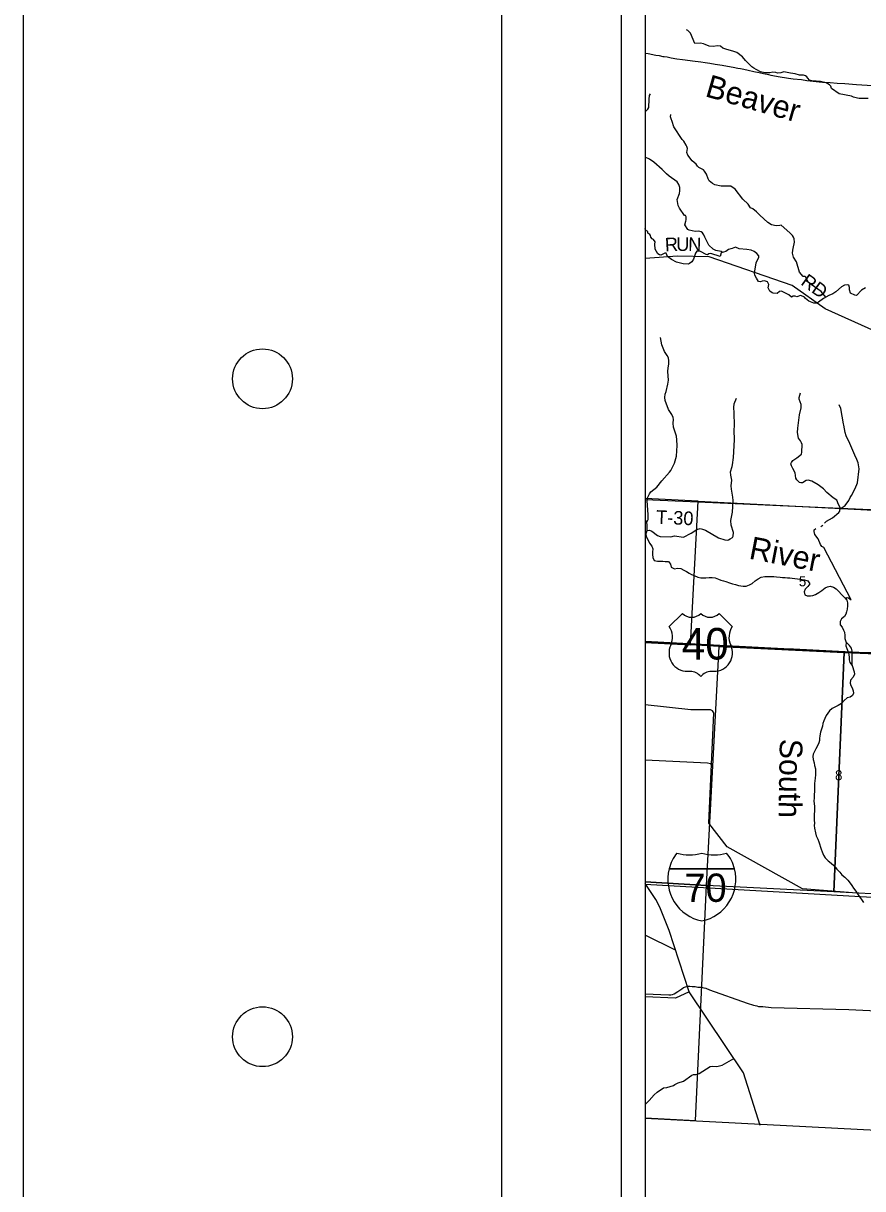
# Model space of a CAD drawing. Extents: x 0 to 40.4, y 0 to 22.
# Drawn here: x 0 to 3.509, y 14.615 to 19.486 of the extents above; entities that cross this region are included whole.
import ezdxf

# ---------------------------------------------------------------- set-up
doc = ezdxf.new("R2010")
doc.units = 0
for name, color, linetype in [('GM_X_County', 7, 'Continuous'), ('GM_X_County_Road', 7, 'Continuous'), ('GM_X_Interstate_Route', 7, 'Continuous'), ('GM_X_Interstate_Shield', 7, 'Continuous'), ('GM_X_Major_River', 7, 'Continuous'), ('GM_X_Major_River_Text', 7, 'Continuous'), ('GM_X_Minor_River', 7, 'Continuous'), ('GM_X_Minor_River_Text', 7, 'Continuous'), ('GM_X_Section', 7, 'Continuous'), ('GM_X_Section_Text', 7, 'Continuous'), ('GM_X_Township_Road', 7, 'Continuous'), ('GM_X_Township_Road_Text', 7, 'Continuous'), ('GM_X_US_Route', 7, 'Continuous'), ('GM_X_US_Shield', 7, 'Continuous'), ('SH_Border', 7, 'Continuous'), ('SH_Cut_Line', 7, 'Continuous'), ('SH_Data', 7, 'Continuous')]:
    doc.layers.add(name, color=color, linetype=linetype)

msp = doc.modelspace()

# ---------------------------------------------------------------- linework, layer by layer
at = {"layer": 'GM_X_County'}
for points in [[(2.6, 14.9098), (3.7816, 14.849), (3.7947, 14.8444), (4.3781, 14.8049), (4.5187, 14.7962), (4.7718, 14.7855), (4.9113, 14.7777), (5.1259, 14.7632), (5.4221, 14.7453), (5.6303, 14.7317), (5.757, 14.7237), (5.765, 14.7235), (5.7951, 14.7228), (5.8513, 14.7168), (5.9456, 14.7103), (6.2034, 14.693), (6.2494, 14.69), (6.369, 14.682), (6.4224, 14.6785), (7.5441, 14.6124), (8.0846, 14.9692), (9.4, 14.8681)], [(2.6, 14.9098), (2.6, 14.9098)]]:
    msp.add_lwpolyline(points, dxfattribs=at)
at = {"layer": 'GM_X_County_Road'}
msp.add_lwpolyline([(3.6855, 19.2158), (3.4837, 19.2291), (3.4349, 19.2324), (3.402, 19.2344), (3.3734, 19.2363), (3.3412, 19.2388), (3.3273, 19.24), (3.3014, 19.2425), (3.2749, 19.2458), (3.2536, 19.2489), (3.2184, 19.2527), (3.1992, 19.2553), (3.1899, 19.257), (3.1638, 19.2613), (3.1408, 19.2649), (3.1263, 19.2682), (3.1164, 19.2702), (3.094, 19.2748), (3.0769, 19.2783), (3.0543, 19.2827), (3.0301, 19.288), (3.0117, 19.2922), (2.9984, 19.2949), (2.9865, 19.2973), (2.9669, 19.3013), (2.9435, 19.3056), (2.9219, 19.3092), (2.8921, 19.3139), (2.87, 19.3174), (2.85, 19.3207), (2.8323, 19.3229), (2.7979, 19.3278), (2.7666, 19.3318), (2.7559, 19.3337), (2.7321, 19.3365), (2.7084, 19.3403), (2.6915, 19.3436), (2.6794, 19.3454), (2.6746, 19.3463), (2.6591, 19.3494), (2.6444, 19.3514), (2.6119, 19.3579), (2.6, 19.3601)], dxfattribs=at)
at = {"layer": 'GM_X_Interstate_Route'}
msp.add_lwpolyline([(2.6, 15.8882), (3.6952, 15.8249), (3.7567, 15.8254), (4.0998, 15.8089), (4.2342, 15.8011)], dxfattribs=at)
at = {"layer": 'GM_X_Interstate_Shield'}
for p, q in [((2.6999, 15.9513), (2.9732, 15.9513)), ((2.9732, 15.9513), (2.6999, 15.9513)), ((2.9732, 15.9513), (2.6999, 15.9513))]:
    msp.add_line(p, q, dxfattribs=at)
for centre, start, end in [((2.872, 15.9078), 141.669, 165.8066), ((2.7846, 16.1877), 253.0091, 286.9909), ((2.8884, 16.1877), 253.0091, 286.9909), ((2.801, 15.9078), 14.1934, 38.331), ((2.872, 15.9078), 165.8066, 258.463), ((2.801, 15.9078), 281.537, 14.1934)]:
    msp.add_arc(centre, 0.1776, start, end, dxfattribs=at)
at = {"layer": 'GM_X_Major_River'}
for points in [[(2.6, 17.4091), (2.6035, 17.4036), (2.6073, 17.3903), (2.6073, 17.377), (2.6065, 17.3649), (2.602, 17.352), (2.6042, 17.3402), (2.6107, 17.3285), (2.6183, 17.3125), (2.627, 17.3008), (2.6312, 17.2886), (2.6304, 17.2757), (2.6308, 17.2659), (2.6315, 17.253), (2.6376, 17.2405), (2.6516, 17.2378), (2.6611, 17.2374), (2.674, 17.2374), (2.6835, 17.2366), (2.6968, 17.2359), (2.7059, 17.2253), (2.7089, 17.212), (2.7229, 17.2063), (2.7355, 17.2078), (2.7483, 17.2067), (2.762, 17.2002), (2.7726, 17.1941), (2.7836, 17.1881), (2.7939, 17.1816), (2.8049, 17.1774), (2.8193, 17.171), (2.8322, 17.1676), (2.8424, 17.1679), (2.8538, 17.1687), (2.8667, 17.1694), (2.8796, 17.1691), (2.8925, 17.1679), (2.9069, 17.163), (2.9164, 17.1588), (2.9266, 17.1554), (2.9368, 17.1523), (2.952, 17.1467), (2.9645, 17.1436), (2.9774, 17.1402), (2.9899, 17.1364), (2.9998, 17.1341), (3.0093, 17.1337), (3.0218, 17.1333), (3.0362, 17.1383), (3.0468, 17.144), (3.0593, 17.155), (3.0722, 17.1633), (3.0848, 17.1705), (3.0996, 17.1731), (3.1128, 17.1743), (3.1257, 17.1735), (3.1379, 17.1731), (3.1489, 17.1724), (3.1637, 17.1705), (3.1735, 17.1697), (3.1849, 17.1689), (3.1951, 17.1686), (3.2046, 17.1674), (3.2149, 17.167), (3.2255, 17.1655), (3.2365, 17.1644), (3.2471, 17.1629), (3.2566, 17.1613), (3.2664, 17.1598), (3.2797, 17.156), (3.2877, 17.1431), (3.2797, 17.1325), (3.2687, 17.1207), (3.2649, 17.1101), (3.2672, 17.0972), (3.2771, 17.0927), (3.2911, 17.0927), (3.3006, 17.0942), (3.3116, 17.098), (3.3264, 17.1063), (3.3389, 17.115), (3.3525, 17.1268)], [(3.3525, 17.1268), (3.362, 17.1306), (3.3726, 17.1332), (3.387, 17.1287), (3.3984, 17.1222), (3.4094, 17.1108), (3.4208, 17.0987), (3.4326, 17.0862), (3.4428, 17.0752), (3.4455, 17.063), (3.4454, 17.0509), (3.4447, 17.0372), (3.442, 17.0255), (3.4382, 17.0156), (3.4329, 17.0061), (3.4208, 16.9974), (3.4151, 16.9853), (3.4151, 16.972), (3.4231, 16.9618), (3.4295, 16.95), (3.4333, 16.9405), (3.4341, 16.9272), (3.434, 16.914), (3.4394, 16.898)], [(3.4394, 16.898), (3.4386, 16.8844), (3.4431, 16.8726), (3.4485, 16.859), (3.4507, 16.848), (3.4519, 16.8351), (3.4526, 16.8256), (3.4557, 16.8146), (3.4651, 16.8013)], [(3.4651, 16.8013), (3.4648, 16.8142), (3.4648, 16.8616), (3.4629, 16.8737), (3.4538, 16.8859), (3.4428, 16.8969), (3.4394, 16.898)], [(3.4651, 16.8013), (3.4735, 16.7747), (3.4742, 16.7653), (3.4697, 16.7531), (3.4587, 16.7402), (3.456, 16.7277), (3.4591, 16.7182), (3.4644, 16.7084), (3.4697, 16.6958), (3.4704, 16.686), (3.4659, 16.6761), (3.4564, 16.6697), (3.4443, 16.6663), (3.4317, 16.6549), (3.42, 16.6424), (3.4071, 16.634), (3.393, 16.6276), (3.382, 16.6215), (3.3699, 16.612), (3.3627, 16.6026), (3.357, 16.5927), (3.3506, 16.5802), (3.3464, 16.5707), (3.343, 16.5586), (3.3407, 16.5487), (3.3365, 16.5358), (3.3323, 16.5233), (3.3293, 16.5081), (3.3289, 16.4971), (3.3278, 16.4876), (3.3259, 16.4782), (3.3206, 16.4656), (3.313, 16.4539), (3.3069, 16.4429), (3.302, 16.4307), (3.3008, 16.4213), (3.3024, 16.4091), (3.3062, 16.3951), (3.308, 16.3841), (3.3111, 16.3704), (3.3115, 16.3572), (3.3115, 16.3446), (3.3103, 16.3306), (3.3088, 16.3192), (3.308, 16.3082), (3.3073, 16.2965), (3.3073, 16.2862), (3.3069, 16.2764), (3.3061, 16.2604), (3.3057, 16.2468), (3.3054, 16.2361), (3.3076, 16.2119), (3.3076, 16.202), (3.3073, 16.1914), (3.3065, 16.1815), (3.3065, 16.155), (3.3069, 16.1432), (3.3061, 16.133), (3.3069, 16.1212), (3.3114, 16.1022), (3.3148, 16.0893), (3.3209, 16.0757), (3.3254, 16.0651), (3.3285, 16.0556), (3.3323, 16.043), (3.3353, 16.0336), (3.3399, 16.0222), (3.3452, 16.0085), (3.3516, 15.9979), (3.3645, 15.9858), (3.377, 15.9751), (3.388, 15.9653), (3.4005, 15.9501), (3.413, 15.9376), (3.4225, 15.9266), (3.4347, 15.9167), (3.4464, 15.9042), (3.457, 15.8913), (3.4631, 15.8818), (3.4703, 15.8712), (3.4802, 15.8583), (3.4878, 15.8469), (3.4957, 15.8343), (3.5041, 15.8233), (3.5124, 15.8104)]]:
    msp.add_lwpolyline(points, dxfattribs=at)
at = {"layer": 'GM_X_Minor_River'}
for points in [[(3.5326, 19.1712), (3.4943, 19.1721), (3.4871, 19.1729), (3.4708, 19.1775), (3.4617, 19.1817), (3.4113, 19.1917), (3.3792, 19.2138), (3.3758, 19.2233), (3.3709, 19.229), (3.3557, 19.2367), (3.3322, 19.2432), (3.2958, 19.2456), (3.2871, 19.2487), (3.2799, 19.2563), (3.2754, 19.262), (3.2701, 19.2666), (3.2617, 19.2692), (3.2454, 19.2689), (3.2273, 19.2751), (3.2079, 19.277), (3.1787, 19.2824), (3.167, 19.2783), (3.1525, 19.2776), (3.1461, 19.2803), (3.1336, 19.2822), (3.1207, 19.2781), (3.0998, 19.2782), (3.0816, 19.2828), (3.0631, 19.2923), (3.0536, 19.2985), (3.046, 19.3034), (3.0188, 19.3301), (3.0064, 19.3457), (2.9825, 19.3632), (2.9704, 19.3685), (2.9564, 19.372), (2.9408, 19.3759), (2.9245, 19.382), (2.9143, 19.39), (2.9026, 19.3912), (2.8836, 19.389), (2.8673, 19.3905), (2.8503, 19.397), (2.8431, 19.3993), (2.8309, 19.4024), (2.807, 19.4014), (2.7886, 19.4439), (2.7776, 19.4557), (2.7723, 19.458)], [(2.6, 19.1164), (2.6027, 19.1184), (2.6104, 19.1264), (2.6146, 19.1332), (2.6162, 19.1692), (2.6185, 19.1844), (2.6216, 19.1908)], [(3.3552, 18.341), (3.3349, 18.3644), (3.2937, 18.3945), (3.2816, 18.4056), (3.2751, 18.4151), (3.2718, 18.4253), (3.2665, 18.4276), (3.2608, 18.4269), (3.2449, 18.4463), (3.2322, 18.4892), (3.2193, 18.5082), (3.2163, 18.5249), (3.2164, 18.5374), (3.2183, 18.545), (3.2245, 18.5708), (3.223, 18.5848), (3.22, 18.5917), (3.2155, 18.5985), (3.2049, 18.6095), (3.1678, 18.6419), (3.1629, 18.6408), (3.1473, 18.6393), (3.1284, 18.6439), (3.1121, 18.6527), (3.0788, 18.6832), (3.0656, 18.6977), (3.0501, 18.7098), (3.0402, 18.7141), (3.0297, 18.7293), (3.0077, 18.7506), (2.9753, 18.7932), (2.9578, 18.805), (2.9529, 18.805), (2.9457, 18.8054), (2.9173, 18.8051), (2.8915, 18.8109), (2.8816, 18.8163), (2.8676, 18.8277), (2.8624, 18.8361), (2.8556, 18.8554), (2.8481, 18.8676), (2.8435, 18.8733), (2.8246, 18.8829), (2.8178, 18.8893), (2.8129, 18.8966), (2.7955, 18.9114), (2.7777, 18.9346), (2.7744, 18.9456), (2.7767, 18.9631), (2.7745, 18.9714), (2.7707, 18.9767), (2.7609, 18.9931), (2.7548, 18.9999), (2.719, 19.0535), (2.7126, 19.0748), (2.7077, 19.0866), (2.7062, 19.0945), (2.707, 19.1044)], [(2.9228, 18.5285), (2.9171, 18.5317), (2.8947, 18.5367), (2.8841, 18.5421), (2.8656, 18.5588), (2.8498, 18.5919), (2.8453, 18.6021), (2.8392, 18.6105), (2.8335, 18.6143), (2.8241, 18.6166), (2.8093, 18.6163), (2.7842, 18.6209), (2.7782, 18.624), (2.7657, 18.643), (2.7692, 18.6589), (2.7704, 18.6638), (2.7708, 18.6771), (2.7685, 18.6824), (2.7636, 18.6821), (2.7428, 18.7136), (2.7379, 18.7239), (2.7331, 18.7497), (2.7427, 18.7751), (2.7446, 18.7857), (2.7447, 18.8001), (2.7409, 18.8119), (2.7334, 18.8229), (2.6997, 18.8473), (2.6891, 18.8568), (2.6709, 18.8751), (2.6358, 18.9052), (2.6176, 18.9185), (2.6, 18.9262)], [(3.2271, 18.3447), (3.218, 18.3448), (3.2115, 18.3406), (3.1998, 18.3513), (3.1695, 18.3666), (3.1612, 18.3651), (3.1509, 18.3568), (3.135, 18.3572), (3.13, 18.3587), (3.1202, 18.3667), (3.1138, 18.38), (3.1161, 18.3944), (3.1112, 18.4051), (3.0991, 18.4097), (3.0889, 18.4086), (3.0813, 18.4059), (3.0737, 18.4071), (3.0692, 18.4132), (3.065, 18.42), (3.0579, 18.4337), (3.0571, 18.4413), (3.0633, 18.4849), (3.0744, 18.5084), (3.0748, 18.5141), (3.0669, 18.5232), (3.0559, 18.5319), (3.0427, 18.5369), (3.0252, 18.5408), (2.993, 18.5436), (2.9771, 18.5497), (2.963, 18.5452), (2.9573, 18.5429), (2.9482, 18.5407), (2.9376, 18.5324), (2.9178, 18.5271), (2.9128, 18.5112), (2.8738, 18.5243), (2.8662, 18.522), (2.8605, 18.5179), (2.8548, 18.519), (2.8314, 18.532), (2.8162, 18.534), (2.8101, 18.5256), (2.8017, 18.5006), (2.7948, 18.4889), (2.7849, 18.4814), (2.78, 18.4791), (2.7591, 18.4807), (2.7307, 18.4876), (2.7095, 18.4983), (2.6932, 18.5113), (2.6876, 18.5253), (2.6819, 18.5254), (2.6652, 18.5171), (2.6591, 18.5175), (2.653, 18.522), (2.6414, 18.5422), (2.6399, 18.5631), (2.6415, 18.5729), (2.6339, 18.5817), (2.6286, 18.5855), (2.6237, 18.5923), (2.6226, 18.5984), (2.6192, 18.6037), (2.6112, 18.6087), (2.6105, 18.6163), (2.601, 18.6216), (2.6, 18.628)], [(3.5212, 18.3797), (3.5041, 18.3706), (3.4832, 18.348), (3.4756, 18.3495), (3.4578, 18.3575), (3.4544, 18.3723), (3.4533, 18.3811), (3.4507, 18.3917), (3.4446, 18.3925), (3.4336, 18.391), (3.4211, 18.3842), (3.3971, 18.3631), (3.3842, 18.3552), (3.3682, 18.348), (3.345, 18.3356), (3.3237, 18.3201), (3.315, 18.316), (3.3048, 18.316), (3.2839, 18.324), (3.2703, 18.3351), (3.2658, 18.3408), (3.2609, 18.3442), (3.2484, 18.3488), (3.2332, 18.342), (3.2271, 18.3447)], [(2.6053, 17.3973), (2.6128, 17.4113), (2.6125, 17.4333), (2.6078, 17.4898), (2.6101, 17.5031), (2.6185, 17.5194), (2.6238, 17.5269), (2.6486, 17.5473), (2.6691, 17.573), (2.7015, 17.6093), (2.7072, 17.6161), (2.7225, 17.6472), (2.7309, 17.676), (2.733, 17.7211), (2.7323, 17.7454), (2.7301, 17.7602), (2.7185, 17.7974), (2.7166, 17.8141), (2.7182, 17.8304), (2.7171, 17.8387), (2.7114, 17.8501), (2.6979, 17.8718), (2.6828, 17.9094), (2.6821, 17.9223), (2.684, 17.936), (2.6875, 17.9473), (2.6948, 17.9773), (2.6971, 17.9943), (2.6946, 18.0304), (2.6962, 18.0459), (2.6989, 18.0618), (2.6993, 18.0755), (2.6971, 18.0869), (2.6922, 18.0971), (2.6801, 18.1146), (2.6688, 18.1423), (2.6632, 18.1723)], [(3.3494, 17.3969), (3.3574, 17.4044), (3.3825, 17.4187), (3.4099, 17.441), (3.4141, 17.4467), (3.4145, 17.4619), (3.4085, 17.4752), (3.401, 17.4923), (3.3854, 17.5029), (3.3597, 17.525), (3.3454, 17.5406), (3.3227, 17.557), (3.2962, 17.5723), (3.2806, 17.5757), (3.2723, 17.5746), (3.2571, 17.5656), (3.2506, 17.5649), (3.2449, 17.5668), (3.2332, 17.5782), (3.2298, 17.5847), (3.2265, 17.6067), (3.2174, 17.6245), (3.2144, 17.6306), (3.211, 17.6355), (3.2088, 17.6439), (3.2111, 17.6503), (3.2168, 17.6587), (3.2339, 17.6692), (3.2529, 17.6843), (3.2552, 17.6934), (3.2557, 17.7257), (3.2535, 17.7329), (3.2493, 17.7408), (3.241, 17.7515), (3.2369, 17.7758), (3.2377, 17.794), (3.2444, 17.849), (3.2524, 17.8785), (3.2517, 17.8925), (3.2435, 17.9153), (3.2439, 17.9222), (3.2489, 17.9411)], [(2.6066, 17.3657), (2.6176, 17.3677), (2.6282, 17.3631), (2.6509, 17.3448), (2.663, 17.3402), (2.707, 17.3393), (2.7222, 17.343), (2.7598, 17.3379), (2.7924, 17.3545), (2.8152, 17.3696), (2.8293, 17.3741), (2.8395, 17.3718), (2.8513, 17.3668), (2.9062, 17.3355), (2.9323, 17.3274), (2.9422, 17.3259), (2.9475, 17.3266), (2.9555, 17.3304), (2.9646, 17.3368), (2.9676, 17.3425), (2.9688, 17.3569), (2.9591, 17.3877), (2.9576, 17.4074), (2.9646, 17.4426), (2.9674, 17.4919), (2.9663, 17.5052), (2.96, 17.5382), (2.9596, 17.5523), (2.962, 17.5761), (2.9575, 17.597), (2.9568, 17.6107), (2.9629, 17.633), (2.9649, 17.6406), (2.9695, 17.6709), (2.9732, 17.7445), (2.9718, 17.7851), (2.9734, 17.8048), (2.9713, 17.8575), (2.9702, 17.8799), (2.9722, 17.8955), (2.9817, 17.9186)], [(3.4144, 17.4571), (3.4354, 17.4705), (3.451, 17.4917), (3.4564, 17.5038), (3.4625, 17.5121), (3.4781, 17.5417), (3.4873, 17.5651), (3.4943, 17.6235), (3.4899, 17.6482), (3.4846, 17.6626), (3.4756, 17.6809), (3.4553, 17.7291), (3.4398, 17.761), (3.4353, 17.7758), (3.4297, 17.8062), (3.429, 17.8111), (3.4182, 17.8753), (3.4114, 17.8916)], [(3.4392, 17.079), (3.4436, 17.0855), (3.45, 17.0843), (3.4606, 17.0756), (3.346, 17.2948), (3.3385, 17.2994), (3.3328, 17.3074), (3.3234, 17.3317), (3.3094, 17.3496), (3.3064, 17.3617), (3.3065, 17.3686), (3.3126, 17.3742)], [(3.3346, 17.3825), (3.343, 17.3882)], [(3.4852, 15.8507), (3.2574, 15.8689), (2.9423, 16.0442), (2.8657, 16.1424), (2.8866, 16.6032), (2.8813, 16.6115), (2.873, 16.6169), (2.7903, 16.6168), (2.6, 16.6372)], [(2.8767, 16.3862), (2.8726, 16.3912), (2.8597, 16.3931), (2.6, 16.4059)], [(3.0807, 14.879), (3.0101, 15.0998), (2.7832, 15.4378), (2.7003, 15.6946), (2.6608, 15.7922), (2.6438, 15.823), (2.6, 15.8906)], [(2.7272, 15.6113), (2.6, 15.6749)], [(2.7834, 15.4376), (2.7259, 15.4111), (2.6, 15.417)], [(2.6, 14.9668), (2.6159, 14.9832), (2.6369, 15.0074), (2.6498, 15.0184), (2.6757, 15.0361), (2.6908, 15.0383), (2.7186, 15.0466), (2.7239, 15.05), (2.7376, 15.0567), (2.7596, 15.0642), (2.7949, 15.0895), (2.8014, 15.0922), (2.8116, 15.0925), (2.8211, 15.0951), (2.8261, 15.097), (2.8713, 15.1253), (2.8808, 15.1275), (2.8994, 15.1263), (2.9222, 15.1316), (2.9704, 15.1588)]]:
    msp.add_lwpolyline(points, dxfattribs=at)
at = {"layer": 'GM_X_Section'}
for p, q in [((2.6, 17.5002), (2.6, 16.8977)), ((2.6, 16.8977), (2.6, 15.8972)), ((2.6, 15.8972), (2.6, 14.9107))]:
    msp.add_line(p, q, dxfattribs=at)
for points in [[(2.6, 16.8977), (2.7891, 16.8878), (2.8217, 17.4882), (2.6, 17.5002)], [(2.6, 15.8972), (2.8566, 15.8822), (2.9088, 16.8816), (2.7891, 16.8878), (2.6, 16.8977)], [(2.6, 14.9107), (2.8097, 14.9002), (2.8566, 15.8822), (2.6, 15.8972)]]:
    msp.add_lwpolyline(points, dxfattribs=at)
for points in [[(2.8217, 17.4882), (3.7188, 17.4429), (3.6994, 16.8455), (3.4311, 16.856), (2.9088, 16.8816), (2.7891, 16.8878)], [(3.4311, 16.856), (3.3882, 15.8552), (2.8566, 15.8822), (2.9088, 16.8816)], [(3.6994, 16.8455), (3.9609, 16.8328), (3.9098, 15.8281), (3.3882, 15.8552), (3.4311, 16.856)]]:
    msp.add_lwpolyline(points, close=True, dxfattribs=at)
at = {"layer": 'GM_X_Township_Road'}
for points in [[(4.759, 18.178), (4.7255, 18.1738), (4.5761, 18.1725), (4.32, 18.1723), (3.8239, 18.0909), (3.8155, 18.0906), (3.8102, 18.0902), (3.8041, 18.091), (3.795, 18.0929), (3.352, 18.2928), (3.2148, 18.3905), (2.8672, 18.5093), (2.7354, 18.5128), (2.6, 18.5025)], [(4.4859, 17.4056), (4.4431, 17.4123), (4.4091, 17.4206), (4.3923, 17.4227), (4.3672, 17.4238), (4.3555, 17.4234), (4.3471, 17.4218), (4.336, 17.4187), (4.2943, 17.4194), (2.6, 17.494)], [(2.6, 15.4296), (2.6988, 15.4258), (2.7064, 15.4253), (2.7136, 15.4272), (2.7212, 15.4298), (2.7357, 15.4385), (2.7529, 15.4506), (2.7605, 15.4555), (2.7677, 15.4592), (2.7749, 15.4603), (2.7799, 15.4611), (2.7867, 15.4614), (2.7966, 15.4606), (2.8091, 15.4602), (2.8205, 15.4575), (2.8346, 15.4567), (2.8456, 15.454), (2.854, 15.4524), (2.8691, 15.4459), (3.0266, 15.3906), (3.0524, 15.3818), (3.06, 15.3802), (3.0672, 15.3787), (3.0733, 15.3771), (3.0798, 15.3767), (3.0866, 15.3763), (3.0915, 15.3759), (3.1265, 15.3727), (3.4516, 15.3644), (3.6869, 15.3532)]]:
    msp.add_lwpolyline(points, dxfattribs=at)
at = {"layer": 'GM_X_US_Route'}
for points in [[(2.6, 16.9029), (2.7567, 16.8949), (2.9116, 16.8872), (3.2062, 16.872)], [(3.2062, 16.872), (3.2196, 16.8713), (3.4616, 16.859), (3.5232, 16.8565), (3.639, 16.856), (3.7926, 16.8594), (4.1165, 16.8674)]]:
    msp.add_lwpolyline(points, dxfattribs=at)
at = {"layer": 'GM_X_US_Shield'}
for p, q in [((2.7551, 17.019), (2.7001, 16.964)), ((2.9638, 16.964), (2.9089, 17.019)), ((2.777, 16.7773), (2.788, 16.7773)), ((2.8759, 16.7773), (2.8869, 16.7773))]:
    msp.add_line(p, q, dxfattribs=at)
for centre, radius, start, end in [((2.7935, 17.0582), 0.0549, 225.573, 314.427), ((2.8704, 17.0582), 0.0549, 225.573, 314.427), ((2.6371, 16.9199), 0.0769, 334.5471, 35.0009), ((3.0268, 16.9199), 0.0769, 144.9991, 205.4529), ((2.7762, 16.8542), 0.0769, 154.8319, 270.6383), ((2.8878, 16.8542), 0.0769, 269.3617, 25.1681), ((2.788, 16.7223), 0.0549, 36.8699, 90), ((2.8759, 16.7223), 0.0549, 90, 143.1301)]:
    msp.add_arc(centre, radius, start, end, dxfattribs=at)
at = {"layer": 'SH_Border'}
msp.add_lwpolyline([(2, 21.5), (33.5, 21.5), (33.5, 0.5), (2, 0.5)], close=True, dxfattribs=at)
for centre in [(1, 18), (1, 15.25)]:
    msp.add_circle(centre, 0.125, dxfattribs=at)
at = {"layer": 'SH_Cut_Line'}
msp.add_lwpolyline([(0, 0), (34, 0), (34, 22), (0, 22)], close=True, dxfattribs=at)
at = {"layer": 'SH_Data'}
for p, q in [((2.5, 21), (2.5, 14)), ((2.6, 20.9), (2.6, 14.1))]:
    msp.add_line(p, q, dxfattribs=at)

# ---------------------------------------------------------------- texts
at = {"layer": 'GM_X_Interstate_Shield'}
msp.add_text('70', height=0.11837, dxfattribs=at).set_placement((2.7643, 15.8137))
at = {"layer": 'GM_X_Major_River_Text'}
for s, height, rotation, p in [('River', 0.09469, 348.9982, (3.0301, 17.2488)), ('South', 0.09471, 269.0008, (3.1629, 16.4961))]:
    msp.add_text(s, height=height, rotation=rotation, dxfattribs=at).set_placement(p)
at = {"layer": 'GM_X_Minor_River_Text'}
msp.add_text('Beaver', height=0.09469, rotation=343.9966, dxfattribs=at).set_placement((2.8462, 19.1816))
at = {"layer": 'GM_X_Section_Text'}
for s, p in [('5', (3.242, 17.1327)), ('8', (3.3932, 16.3221))]:
    msp.add_text(s, height=0.0419, rotation=0, dxfattribs=at).set_placement(p)
at = {"layer": 'GM_X_Township_Road_Text'}
for s, height, rotation, p in [('R', 0.0568, 3.0027, (2.6836, 18.5319)), ('U', 0.0568, 359.898, (2.7294, 18.5343)), ('N', 0.0568, 358.6593, (2.7791, 18.5342)), ('RD', 0.05682, 324.52, (3.2466, 18.3961)), ('T-30', 0.05682, 357.5258, (2.6444, 17.3944))]:
    msp.add_text(s, height=height, rotation=rotation, dxfattribs=at).set_placement(p)
at = {"layer": 'GM_X_US_Shield'}
msp.add_text('40', height=0.13184, dxfattribs=at).set_placement((2.7528, 16.8267))

doc.saveas('drawing.dxf')
